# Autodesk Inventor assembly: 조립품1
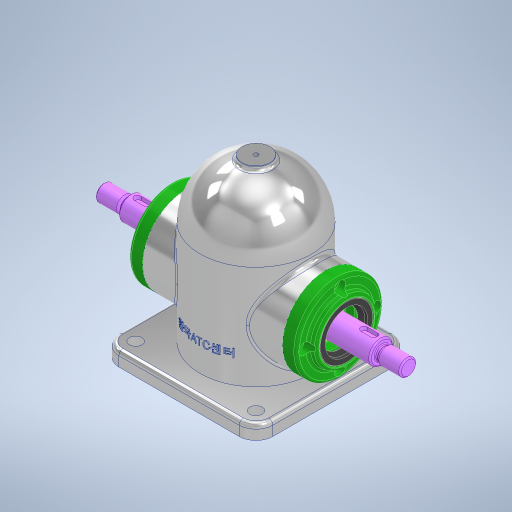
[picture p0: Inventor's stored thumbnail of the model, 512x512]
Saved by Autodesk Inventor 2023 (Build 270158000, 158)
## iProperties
Created: 2025-04
Part Number: 조립품1
Document SubType Name: Assembly
Designer: ADMIN_PC
Author: ADMIN_PC
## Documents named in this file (6)
- C:\Users\ADMIN_PC\Desktop\750406V1010\조립품1.iam
- C:\Users\ADMIN_PC\Desktop\750406V1010\부품.ipt
- C:\Users\ADMIN_PC\Desktop\750406V1010\깊은 홈 볼 베어링 6203.ipt
- C:\Users\ADMIN_PC\Desktop\750406V1010\축.ipt
- C:\Users\ADMIN_PC\Desktop\750406V1010\커버.ipt
- C:\Users\ADMIN_PC\Desktop\750406V1010\오일 실 26 38 8.ipt
